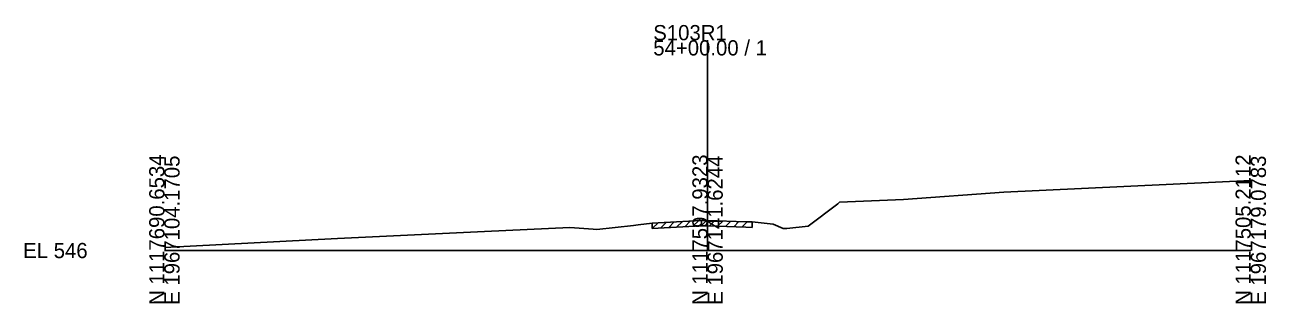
# Model space of a CAD drawing. Extents: x -26 to 203, y -10 to 12018.
# Drawn here: x -25.7 to 202.8, y 1490.3 to 1541.6 of the extents above; entities that cross this region are included whole.
import ezdxf

# ---------------------------------------------------------------- set-up
doc = ezdxf.new("R2010")
doc.units = 0
for name, color, linetype in [('Level 60', 7, 'Continuous'), ('Level 61', 7, 'Continuous'), ('Level 63', 7, 'Continuous')]:
    doc.layers.add(name, color=color, linetype=linetype)

msp = doc.modelspace()

# ---------------------------------------------------------------- linework, layer by layer
at = {"layer": 'Level 60'}
for p, q in [((154.54, 1510.72), (200, 1512.91)), ((136.09, 1509.38), (154.54, 1510.72)), ((118.54, 1504.48), (123.97, 1508.63)), ((123.97, 1508.63), (124.3, 1508.9)), ((124.3, 1508.9), (136.09, 1509.38)), ((58.94, 1503.53), (74.67, 1504.27)), ((74.67, 1504.27), (78.93, 1503.94)), ((78.93, 1503.94), (79.62, 1503.88)), ((79.62, 1503.88), (86.38, 1504.64)), ((86.38, 1504.64), (87.22, 1504.74)), ((87.22, 1504.74), (89.81, 1505.03)), ((89.81, 1505.03), (90.9, 1505.1)), ((90.9, 1505.1), (98.85, 1505.56)), ((98.85, 1505.56), (100, 1505.52)), ((100, 1505.52), (107.05, 1505.3)), ((107.05, 1505.3), (108.23, 1505.27)), ((108.23, 1505.27), (108.75, 1505.21)), ((108.75, 1505.21), (112.1, 1504.85)), ((112.1, 1504.85), (113.93, 1504.03)), ((113.93, 1504.03), (114.62, 1504.08)), ((114.62, 1504.08), (118.54, 1504.48)), ((0, 1500.58), (31.85, 1502.23)), ((31.85, 1502.23), (58.94, 1503.53))]:
    msp.add_line(p, q, dxfattribs=at)
at = {"layer": 'Level 61'}
for p, q in [((89.81, 1504.03), (90.88, 1505.1)), ((89.81, 1504.03), (89.81, 1505.03)), ((89.81, 1504.03), (90.9, 1504.1)), ((90.9, 1504.1), (98.85, 1504.56)), ((91.31, 1504.12), (92.37, 1505.19)), ((92.81, 1504.21), (93.87, 1505.27)), ((94.31, 1504.3), (95.37, 1505.36)), ((95.81, 1504.38), (96.87, 1505.44)), ((97.31, 1504.47), (98.37, 1505.53)), ((98.81, 1504.56), (99.79, 1505.53)), ((98.85, 1504.56), (100, 1504.52)), ((100, 1504.52), (107.05, 1504.3)), ((100.31, 1504.51), (101.28, 1505.48)), ((101.81, 1504.46), (102.78, 1505.43)), ((103.31, 1504.42), (104.28, 1505.39)), ((104.81, 1504.37), (105.78, 1505.34)), ((106.31, 1504.32), (107.28, 1505.29)), ((107.05, 1504.3), (108.23, 1504.27)), ((108.23, 1505.27), (108.23, 1504.27))]:
    msp.add_line(p, q, dxfattribs=at)
at = {"layer": 'Level 63'}
for p, q in [((100, 1500), (100, 1538.72)), ((0, 1500), (100, 1500)), ((100, 1500), (200, 1500))]:
    msp.add_line(p, q, dxfattribs=at)

# ---------------------------------------------------------------- texts
for s, p in [('S103R1', (90, 1538.72)), ('54+00.00 / 1', (90, 1535.92)), ('EL 546', (-26, 1498.6))]:
    msp.add_text(s, height=2.8, dxfattribs=at).set_placement(p)
for s, p in [('N 1117690.6534', (0, 1490)), ('N 1117597.9323', (100, 1490)), ('N 1117505.2112', (200, 1490)), ('E 1967104.1705', (2.8, 1490)), ('E 1967141.6244', (102.8, 1490)), ('E 1967179.0783', (202.8, 1490))]:
    msp.add_text(s, height=2.8, rotation=90, dxfattribs=at).set_placement(p)

doc.saveas('drawing.dxf')
